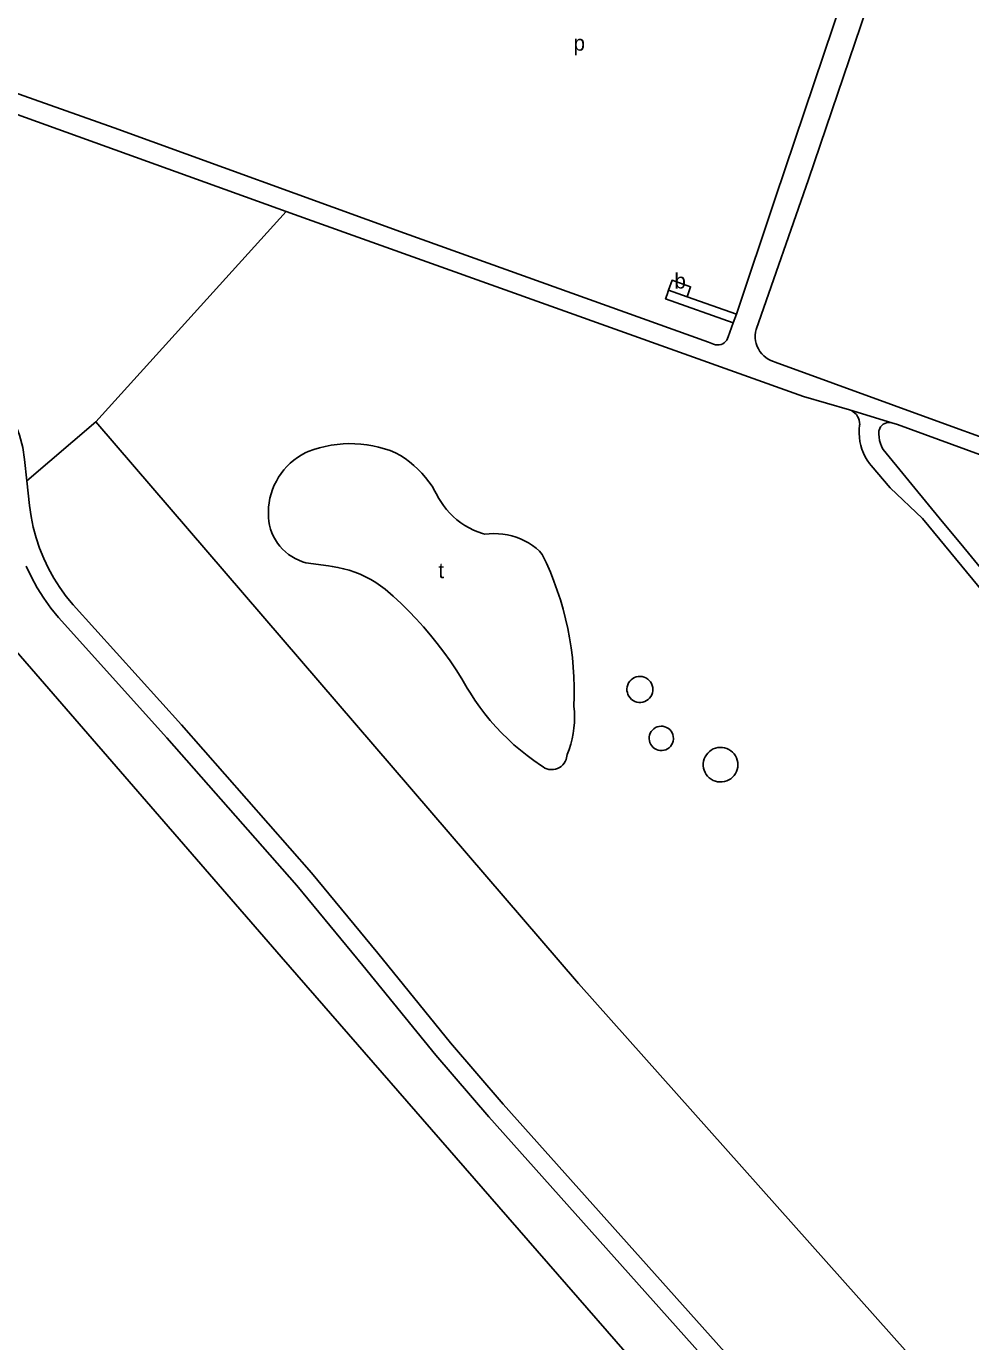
# Model space of a CAD drawing. Extents: x 156066 to 157805, y 383432 to 385631.
# Drawn here: x 156377.3 to 156622.4, y 384832 to 385173.1 of the extents above; entities that cross this region are included whole.
import ezdxf

# ---------------------------------------------------------------- set-up
doc = ezdxf.new("R2010")
doc.units = 0
for name, color, linetype in [('BLT_Basislijn', 7, 'Continuous'), ('BLT_Bebouwing', 7, 'Continuous'), ('BLT_Centroide', 7, 'Continuous')]:
    doc.layers.add(name, color=color, linetype=linetype)

msp = doc.modelspace()

# ---------------------------------------------------------------- linework, layer by layer
at = {"layer": 'BLT_Basislijn'}
for p, q in [((156600.14, 385213.08), (156571.69, 385128.4)), ((156320.75, 385169.82), (156444.74, 385125.05)), ((156400.12, 385146.74), (156475.52, 385119.48)), ((156561.61, 385098.4), (156571.69, 385128.4)), ((156444.74, 385125.05), (156450.29, 385123.05)), ((156554.39, 385091.19), (156475.52, 385119.48)), ((156544.01, 385104.64), (156543.61, 385103.51)), ((156548.8, 385102.96), (156561.61, 385098.4)), ((156560.73, 385096.22), (156559.48, 385092.59)), ((156560.73, 385096.22), (156561.61, 385098.4)), ((156554.39, 385091.19), (156555.67, 385090.69)), ((156617.54, 385069.34), (156571.71, 385085.99)), ((156590.93, 385073.63), (156601.92, 385070.3)), ((156395.43, 385070.56), (156377.45, 385055.22)), ((156603.38, 385069.8), (156601.92, 385070.3)), ((156603.38, 385069.8), (156628.27, 385060.73)), ((156624.71, 385066.73), (156617.54, 385069.34)), ((156599.69, 385063.33), (156612.27, 385048.06)), ((156612.27, 385048.06), (156615.45, 385044.2)), ((156609.93, 385045.44), (156628.64, 385022.72)), ((156615.45, 385044.2), (156619.86, 385038.85)), ((156619.86, 385038.85), (156629.74, 385026.88)), ((156455.75, 385033.14), (156449.88, 385033.98)), ((156520.6, 384924.89), (156676.39, 384750.24))]:
    msp.add_line(p, q, dxfattribs=at)
for points in [[(156599.96, 385191.23), (156580.29, 385133.36), (156566.73, 385094.47)], [(156324.02, 385174.01), (156355.85, 385162.45), (156400.12, 385146.74)], [(156444.74, 385125.05), (156395.43, 385070.56)], [(156450.29, 385123.05), (156579.04, 385077.08), (156590.93, 385073.63)], [(156377.45, 385055.22), (156376.85, 385060.73), (156376.41, 385063.87), (156375.61, 385067.06), (156374.43, 385070.13), (156372.89, 385073.05), (156371.05, 385075.7), (156369.12, 385078.11), (156354.18, 385096.89), (156352.2, 385099.33), (156349.92, 385101.67), (156347.34, 385103.72), (156344.54, 385105.47), (156342.38, 385106.48)], [(156543.61, 385103.51), (156543.22, 385102.38), (156560.73, 385096.22)], [(156559.48, 385092.59), (156559.33, 385092.14), (156559.1, 385091.73), (156558.81, 385091.36), (156558.45, 385091.04), (156558.05, 385090.79), (156557.62, 385090.6), (156557.15, 385090.5), (156556.68, 385090.47), (156556.21, 385090.52), (156555.67, 385090.69)], [(156566.73, 385094.47), (156566.58, 385093.74), (156566.51, 385093), (156566.52, 385092.26), (156566.61, 385091.52), (156566.77, 385090.8), (156567.02, 385090.09), (156567.34, 385089.42), (156567.72, 385088.78), (156568.18, 385088.19), (156568.69, 385087.65), (156569.26, 385087.17), (156569.88, 385086.76), (156570.54, 385086.41), (156571.23, 385086.14), (156571.71, 385085.99)], [(156590.93, 385073.63), (156591.44, 385073.42), (156591.92, 385073.14), (156592.36, 385072.8), (156592.74, 385072.39), (156593.05, 385071.94), (156593.3, 385071.44), (156593.48, 385070.92), (156593.58, 385070.37), (156593.6, 385069.82), (156593.59, 385069.65)], [(156395.43, 385070.56), (156520.6, 384924.89)], [(156593.59, 385069.65), (156593.49, 385068.6), (156593.48, 385067.55), (156593.54, 385066.5), (156593.68, 385065.45), (156593.9, 385064.42), (156594.2, 385063.41), (156594.58, 385062.43), (156595.03, 385061.47), (156595.55, 385060.56), (156596.13, 385059.68), (156596.54, 385059.16)], [(156601.92, 385070.3), (156601.46, 385070.38), (156600.99, 385070.37), (156600.54, 385070.28), (156600.1, 385070.12), (156599.7, 385069.88), (156599.34, 385069.58), (156599.04, 385069.22), (156598.8, 385068.82), (156598.64, 385068.38), (156598.59, 385068.16)], [(156598.59, 385068.16), (156598.57, 385067.35), (156598.62, 385066.53), (156598.76, 385065.72), (156598.97, 385064.93), (156599.26, 385064.17), (156599.63, 385063.44), (156599.69, 385063.33)], [(156449.71, 385062.49), (156448.68, 385061.92), (156447.68, 385061.28), (156446.74, 385060.57), (156445.84, 385059.8), (156444.99, 385058.97), (156444.21, 385058.08), (156443.48, 385057.15), (156442.82, 385056.16), (156442.23, 385055.14), (156441.7, 385054.08), (156441.26, 385052.98), (156440.88, 385051.86), (156440.58, 385050.71), (156440.36, 385049.55), (156440.22, 385048.37), (156440.16, 385047.19), (156440.16, 385046.73)], [(156473.18, 385062.49), (156471.74, 385063.06), (156470.27, 385063.55), (156468.77, 385063.97), (156467.25, 385064.31), (156465.72, 385064.57), (156464.18, 385064.75), (156462.63, 385064.85), (156461.08, 385064.87), (156459.53, 385064.81), (156457.98, 385064.67), (156456.44, 385064.45), (156454.92, 385064.16), (156453.41, 385063.78), (156451.93, 385063.33), (156450.47, 385062.8), (156449.71, 385062.49)], [(156473.18, 385062.49), (156474.43, 385061.77), (156475.64, 385060.99), (156476.8, 385060.14), (156477.91, 385059.22), (156478.97, 385058.24), (156479.98, 385057.21), (156480.92, 385056.12), (156481.81, 385054.99), (156482.63, 385053.8), (156483.38, 385052.57), (156484.06, 385051.3), (156484.25, 385050.92)], [(156596.54, 385059.16), (156601.48, 385053.44), (156609.93, 385045.44)], [(156621.03, 384759.41), (156501.09, 384893.58), (156487.46, 384909.46), (156468.56, 384932.75), (156451.32, 384953.57), (156417.58, 384991.92), (156389.52, 385023.04), (156387.7, 385025.27), (156386.01, 385027.6), (156384.49, 385030), (156383.12, 385032.49), (156381.88, 385035.08), (156380.81, 385037.72), (156379.9, 385040.43), (156379.16, 385043.17), (156378.57, 385045.98), (156378.16, 385048.8), (156377.45, 385055.22)], [(156340.3, 385050.65), (156349.3, 385040.29), (156443.48, 384931.76), (156500, 384866.97)], [(156484.25, 385050.92), (156484.9, 385049.83), (156485.61, 385048.79), (156486.39, 385047.79), (156487.23, 385046.85), (156488.13, 385045.96), (156489.08, 385045.13), (156490.09, 385044.36), (156491.14, 385043.66), (156492.23, 385043.02), (156493.36, 385042.45), (156494.52, 385041.96), (156495.72, 385041.54), (156496.32, 385041.36)], [(156440.16, 385046.73), (156440.19, 385045.71), (156440.3, 385044.69), (156440.48, 385043.69), (156440.75, 385042.7), (156441.09, 385041.74), (156441.51, 385040.81), (156441.99, 385039.91), (156442.55, 385039.06), (156443.17, 385038.25), (156443.86, 385037.49), (156444.6, 385036.79), (156445.39, 385036.15), (156446.23, 385035.57), (156447.11, 385035.06), (156448.03, 385034.62), (156448.99, 385034.25), (156449.88, 385033.98)], [(156496.32, 385041.36), (156497.49, 385041.49), (156498.67, 385041.54), (156499.85, 385041.51), (156501.02, 385041.4), (156502.19, 385041.21), (156503.34, 385040.94), (156504.46, 385040.6), (156505.57, 385040.18), (156506.64, 385039.68), (156507.67, 385039.12), (156508.67, 385038.49), (156509.62, 385037.79), (156510.52, 385037.02), (156511.24, 385036.16)], [(156511.24, 385036.16), (156512.32, 385033.86), (156513.34, 385031.53), (156514.28, 385029.16), (156515.14, 385026.77), (156515.93, 385024.35), (156516.64, 385021.91), (156517.28, 385019.45), (156517.84, 385016.96), (156518.32, 385014.47), (156518.72, 385011.95), (156519.04, 385009.43), (156519.28, 385006.9), (156519.44, 385004.36), (156519.53, 385001.82), (156519.53, 384999.27), (156519.45, 384996.75)], [(156617.3, 384756.08), (156497.33, 384890.29), (156483.62, 384906.25), (156464.69, 384929.58), (156447.52, 384950.32), (156413.84, 384988.59), (156385.73, 385019.78), (156383.73, 385022.22), (156381.87, 385024.79), (156380.19, 385027.45), (156378.67, 385030.2), (156377.31, 385033.06)], [(156470.5, 385027.1), (156469.29, 385028.01), (156468.03, 385028.86), (156466.72, 385029.63), (156465.38, 385030.34), (156464, 385030.98), (156462.59, 385031.54), (156461.16, 385032.02), (156459.7, 385032.43), (156458.22, 385032.77), (156456.72, 385033.02), (156455.75, 385033.14)], [(156491.79, 385001.44), (156490.36, 385003.85), (156488.86, 385006.22), (156487.3, 385008.54), (156485.67, 385010.82), (156483.97, 385013.05), (156482.21, 385015.23), (156480.39, 385017.35), (156478.51, 385019.43), (156476.57, 385021.45), (156474.58, 385023.42), (156472.53, 385025.33), (156470.5, 385027.1)], [(156539.93, 385001.13), (156539.89, 385001.65), (156539.77, 385002.15), (156539.58, 385002.63), (156539.31, 385003.08), (156538.98, 385003.48), (156538.59, 385003.82), (156538.15, 385004.1), (156537.68, 385004.3), (156537.18, 385004.44), (156536.66, 385004.49), (156536.14, 385004.47), (156535.64, 385004.36), (156535.15, 385004.18), (156534.7, 385003.93), (156534.29, 385003.61), (156533.94, 385003.23), (156533.65, 385002.8), (156533.43, 385002.33), (156533.28, 385001.83), (156533.21, 385001.32), (156533.22, 385000.8), (156533.31, 385000.29), (156533.48, 384999.8), (156533.72, 384999.34), (156534.03, 384998.92), (156534.4, 384998.56), (156534.82, 384998.26), (156535.28, 384998.02), (156535.78, 384997.86), (156536.29, 384997.78), (156536.81, 384997.78), (156537.32, 384997.85), (156537.81, 384998.01), (156538.28, 384998.24), (156538.7, 384998.54), (156539.08, 384998.89), (156539.39, 384999.31), (156539.64, 384999.76), (156539.81, 385000.25), (156539.91, 385000.76), (156539.93, 385001.13)], [(156511.07, 384981.32), (156509.08, 384982.71), (156507.31, 384984.01), (156505.58, 384985.37), (156503.9, 384986.79), (156502.28, 384988.28), (156500.71, 384989.82), (156499.2, 384991.41), (156497.75, 384993.06), (156496.36, 384994.77), (156495.03, 384996.52), (156493.77, 384998.32), (156492.57, 385000.16), (156491.79, 385001.44)], [(156519.45, 384996.75), (156519.57, 384995.34), (156519.61, 384993.92), (156519.57, 384992.51), (156519.45, 384991.09), (156519.25, 384989.69), (156518.98, 384988.3), (156518.62, 384986.93), (156518.19, 384985.59), (156517.68, 384984.27), (156517.44, 384982.99)], [(156545.28, 384988.44), (156545.24, 384988.94), (156545.12, 384989.43), (156544.93, 384989.89), (156544.66, 384990.32), (156544.33, 384990.7), (156543.95, 384991.02), (156543.51, 384991.28), (156543.05, 384991.46), (156542.55, 384991.57), (156542.05, 384991.6), (156541.55, 384991.55), (156541.07, 384991.42), (156540.61, 384991.22), (156540.19, 384990.94), (156539.82, 384990.6), (156539.5, 384990.21), (156539.25, 384989.78), (156539.08, 384989.3), (156538.98, 384988.81), (156538.96, 384988.31), (156539.02, 384987.81), (156539.16, 384987.33), (156539.37, 384986.87), (156539.65, 384986.46), (156540, 384986.09), (156540.4, 384985.79), (156540.84, 384985.55), (156541.31, 384985.38), (156541.81, 384985.29), (156542.31, 384985.28), (156542.81, 384985.35), (156543.29, 384985.5), (156543.74, 384985.72), (156544.15, 384986.02), (156544.51, 384986.37), (156544.8, 384986.77), (156545.04, 384987.22), (156545.19, 384987.7), (156545.27, 384988.19), (156545.28, 384988.44)], [(156561.99, 384981.61), (156561.95, 384982.21), (156561.83, 384982.8), (156561.64, 384983.37), (156561.37, 384983.9), (156561.03, 384984.4), (156560.63, 384984.84), (156560.17, 384985.23), (156559.66, 384985.55), (156559.12, 384985.8), (156558.55, 384985.98), (156557.96, 384986.08), (156557.36, 384986.1), (156556.76, 384986.04), (156556.18, 384985.91), (156555.62, 384985.69), (156555.1, 384985.41), (156554.61, 384985.05), (156554.18, 384984.64), (156553.81, 384984.17), (156553.5, 384983.65), (156553.27, 384983.1), (156553.1, 384982.53), (156553.02, 384981.93), (156553.02, 384981.33), (156553.1, 384980.74), (156553.25, 384980.16), (156553.48, 384979.61), (156553.79, 384979.09), (156554.15, 384978.62), (156554.58, 384978.2), (156555.06, 384977.84), (156555.59, 384977.55), (156556.15, 384977.33), (156556.73, 384977.19), (156557.32, 384977.13), (156557.92, 384977.15), (156558.51, 384977.24), (156559.09, 384977.41), (156559.63, 384977.66), (156560.14, 384977.98), (156560.6, 384978.36), (156561, 384978.81), (156561.35, 384979.3), (156561.62, 384979.83), (156561.82, 384980.39), (156561.95, 384980.98), (156561.99, 384981.61)], [(156517.44, 384982.99), (156517.22, 384982.48), (156516.93, 384981.99), (156516.57, 384981.56), (156516.16, 384981.18), (156515.69, 384980.86), (156515.19, 384980.61), (156514.65, 384980.44), (156514.1, 384980.34), (156513.53, 384980.33), (156512.98, 384980.39), (156512.43, 384980.53), (156511.91, 384980.74), (156511.43, 384981.03), (156511.07, 384981.32)], [(156500, 384866.97), (156550.9, 384808.49), (156654.32, 384689.66)]]:
    msp.add_lwpolyline(points, dxfattribs=at)
at = {"layer": 'BLT_Bebouwing'}
msp.add_line((156544.01, 385104.64), (156548.8, 385102.96), dxfattribs=at)
msp.add_lwpolyline([(156548.8, 385102.96), (156549.72, 385105.57), (156544.92, 385107.25), (156544.01, 385104.64)], dxfattribs=at)

# ---------------------------------------------------------------- texts
at = {"layer": 'BLT_Centroide'}
for s, p in [('p', (156519.35, 385166.77)), ('b', (156545.53, 385105.09)), ('t', (156484.29, 385029.98))]:
    msp.add_text(s, height=4, dxfattribs=at).set_placement(p)

doc.saveas('drawing.dxf')
